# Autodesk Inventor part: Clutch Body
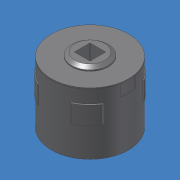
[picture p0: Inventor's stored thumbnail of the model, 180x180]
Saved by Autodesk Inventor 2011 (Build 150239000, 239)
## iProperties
Created: 2007-08
Part Number: Clutch Body
Material: ABS Plastic
Document SubType Name: Modeling
Density: 1.06 g/cm^3
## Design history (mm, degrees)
feature "Base1"
body "Solid1"
